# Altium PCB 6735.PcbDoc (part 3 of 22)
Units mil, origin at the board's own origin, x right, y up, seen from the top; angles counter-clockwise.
Board outline 2641.73 x 5165.35 mil, 6 copper layers (Top, Inner Layer 2, Inner Layer 3, Inner Layer 4, Inner Layer 5, Bottom), stack 35.7 mil thick; 1011 components, 790 nets, 4118 pads, 9325 vias.
Unrouted connection lines stored in the file: 4610.
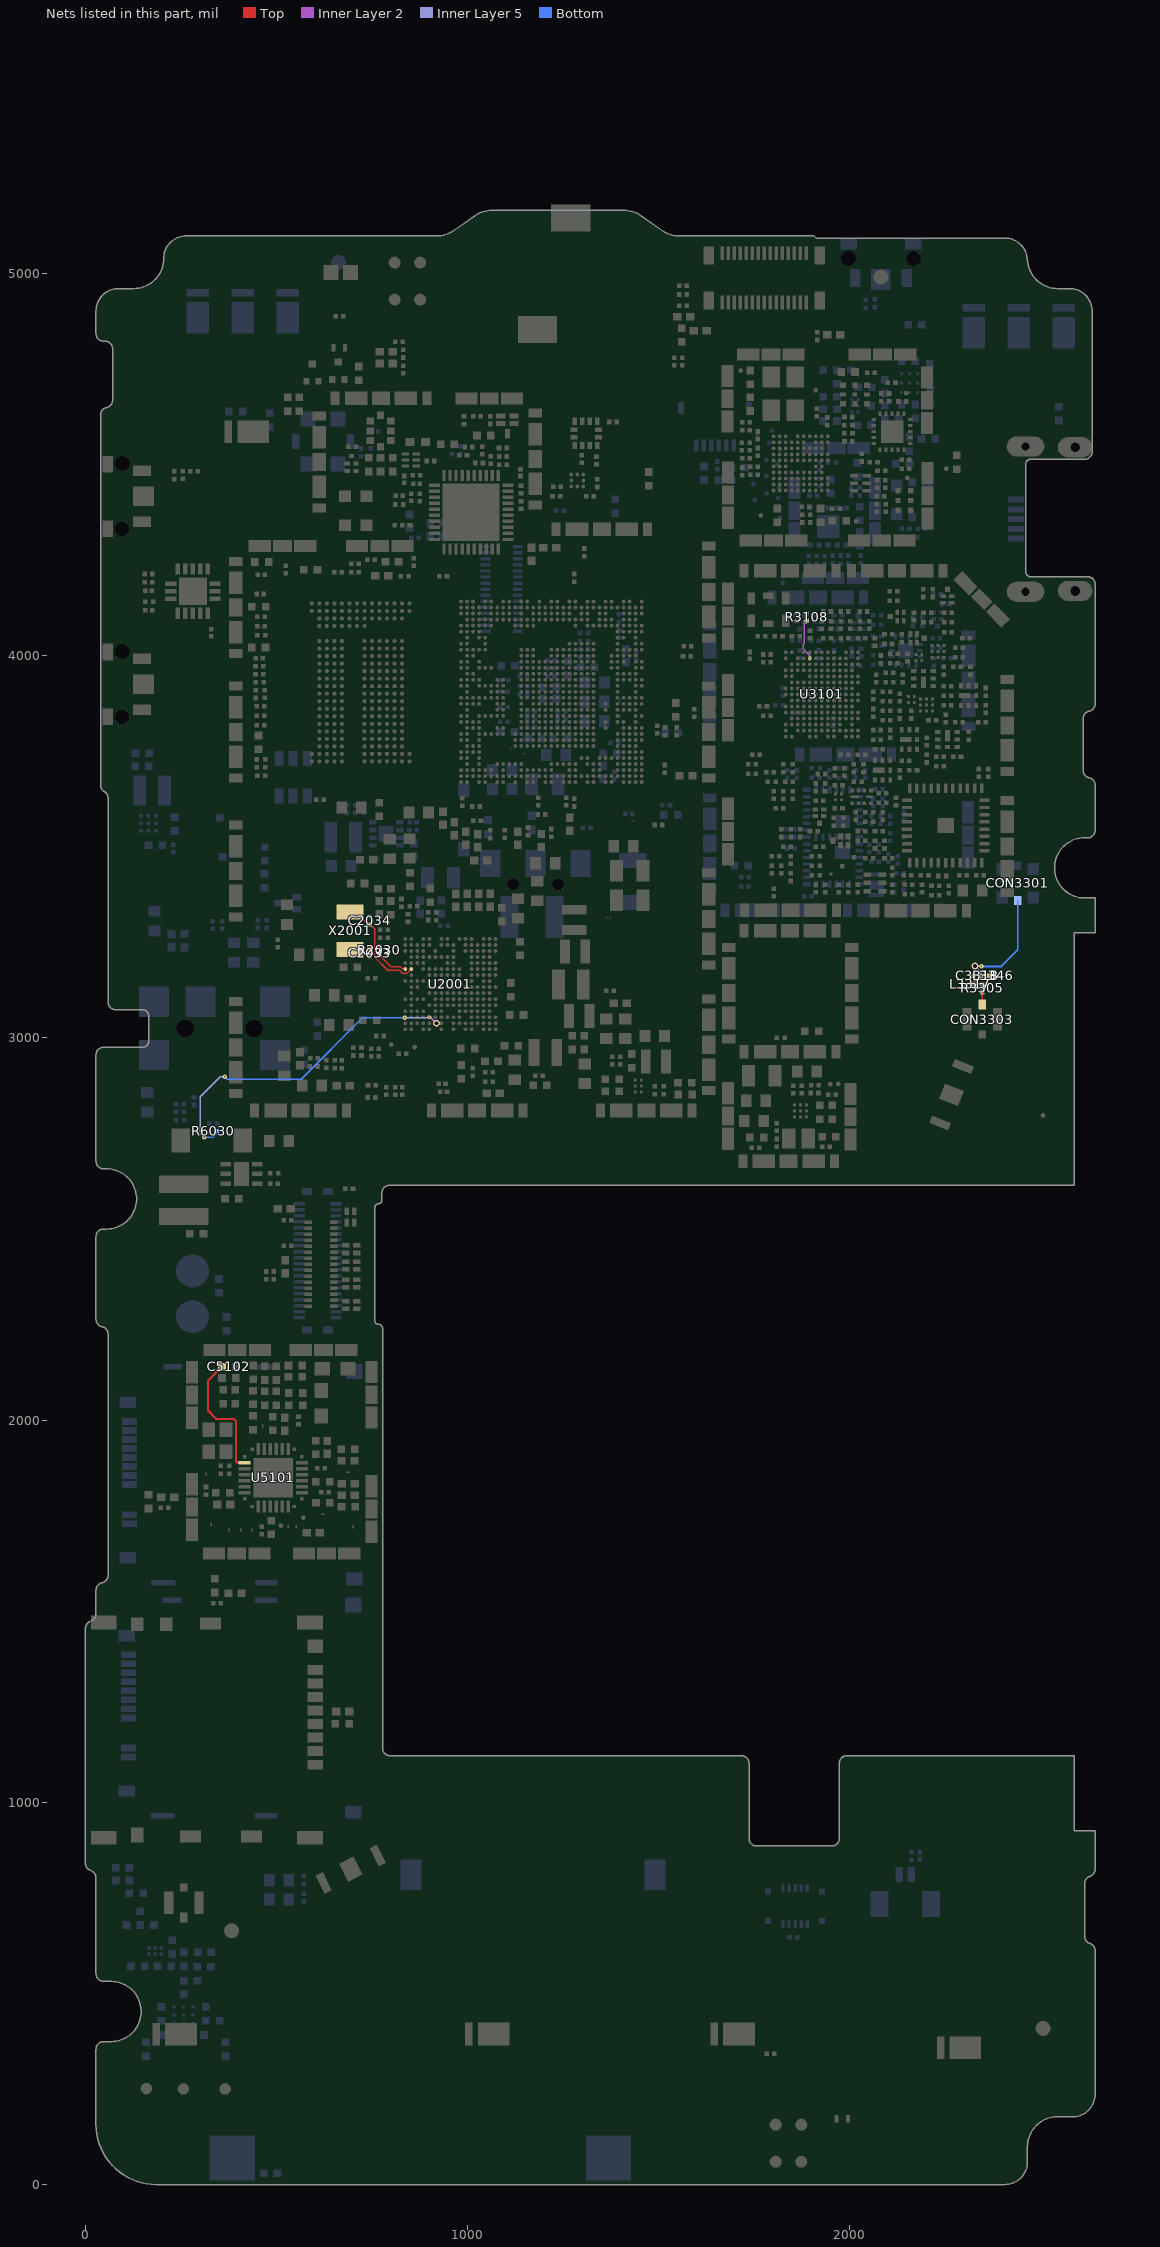
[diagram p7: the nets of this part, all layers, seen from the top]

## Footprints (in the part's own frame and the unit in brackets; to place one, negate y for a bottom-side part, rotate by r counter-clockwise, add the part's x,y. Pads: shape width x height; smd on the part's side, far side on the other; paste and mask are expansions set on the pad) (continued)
AUDIOJACK$2F$5P$2F$SMD$2F$EJ-3699M-GP [mm]
  rect 2x2 smd: 1(0,0) 2(0,-3.55) 3(-3.1,0) 4(-8.05,0) 5(-8.05,-3.55)
  round 1.2 hole 1.2 unplated: 6(-2.05,-1.775) 7(-6.65,-1.775)
  Keep-Out Layer pour cut-out: -1.196,-1.775 -1.261,-1.448 -1.446,-1.171 -1.723,-0.986 -2.05,-0.921 -2.05,-0.921 -2.377,-0.986 -2.654,-1.171 -2.839,-1.448 -2.904,-1.775 -2.904,-1.775 -2.839,-2.102 -2.654,-2.379 -2.377,-2.564 -2.05,-2.629 -2.05,-2.629 -1.723,-2.564 -1.446,-2.379 -1.261,-2.102 -1.196,-1.775
  Keep-Out Layer pour cut-out: -5.796,-1.775 -5.861,-1.448 -6.046,-1.171 -6.323,-0.986 -6.65,-0.921 -6.65,-0.921 -6.977,-0.986 -7.254,-1.171 -7.439,-1.448 -7.504,-1.775 -7.504,-1.775 -7.439,-2.102 -7.254,-2.379 -6.977,-2.564 -6.65,-2.629 -6.65,-2.629 -6.323,-2.564 -6.046,-2.379 -5.861,-2.102 -5.796,-1.775
  silkscreen extent -8.9,-5.3 3.85,1.75
BALUN$2F$SMD$2F$HHM22112A2 [mm]
  rect 0.3x0.5 smd: 1(-0.55,-0.5) 2(0,-0.5) 3(0.55,-0.5) 4(0.55,0.5) 5(0,0.5) 6(-0.55,0.5)
  silkscreen extent -1.15,-0.75 0.9,0.5
BALUN$2F$SMD$2F$TFSZ06051897-3317A1 [mm]
  rect 0.2x0.18 smd: 1(-0.2,-0.19) 2(0.2,-0.19) 3(0.2,0.19) 4(-0.2,0.19)
  silkscreen extent -0.55,-0.53 0.4,0.32
BALUN$2F$SMD$2F$TFSZ06052460-3310A2 [mm]
  rect 0.2x0.18 smd: 1(-0.2,-0.19) 2(0.2,-0.19) 3(0.2,0.19) 4(-0.2,0.19)
  silkscreen extent -0.44,-0.5 0.21,0.38
BAT$2F$SMD$2F$KBC23S3D4XR$2F$KEIRAKU [mm]
  rect 1.35x1.8 smd: 1(3,1.4) 2(0,1.4) 3(-3,1.4)
  rect 1.2x2.79 smd: 4(-1.28,-2.145) 5(1.73,-2.145)
  round 0.8 hole 0.8 unplated: 6(-1.5,0) 7(1.5,0)
  Keep-Out Layer pour cut-out: -0.846,0 -0.896,0.25 -1.038,0.462 -1.25,0.604 -1.5,0.654 -1.5,0.654 -1.75,0.604 -1.962,0.462 -2.104,0.25 -2.154,0 -2.154,0 -2.104,-0.25 -1.962,-0.462 -1.75,-0.604 -1.5,-0.654 -1.5,-0.654 -1.25,-0.604 -1.038,-0.462 -0.896,-0.25 -0.846,0
  Keep-Out Layer pour cut-out: 2.154,0 2.104,0.25 1.962,0.462 1.75,0.604 1.5,0.654 1.5,0.654 1.25,0.604 1.038,0.462 0.896,0.25 0.846,0 0.846,0 0.896,-0.25 1.038,-0.462 1.25,-0.604 1.5,-0.654 1.5,-0.654 1.75,-0.604 1.962,-0.462 2.104,-0.25 2.154,0
  silkscreen extent -4.55,-4.75 4.55,1.4
BEAD0402 [mil]
  rect 24x20 smd: 1(-20,0) 2(20,0)
  silkscreen extent -40,-15 40,15
BEAD0603 [mil]
  rect 28x32 smd: 1(-25.59,0) 2(25.59,0)
  silkscreen extent -48,-25 48,25
C0201 [mil]
  rect 12x12 smd: 1(-10,0) 2(10,0)
  silkscreen extent -20,-10 20,10
C0402 [mil]
  rect 20x20 smd: 1(-18,0) 2(18,0)
  silkscreen extent -33,-15 33,15
C0603 [mil]
  rect 28x32 smd: 1(-25.59,0) 2(25.59,0)
  silkscreen extent -48,-25 48,25
C0805 [mil]
  rect 34x56 smd: 1(-34.45,0) 2(34.45,0)
  silkscreen extent -62,-38 62,38
CABLE_CLIP$2F$3P$2F$SMD$2F$PCV1003 [mm]
  rect 1.35x0.55 smd: 1(0,-2.025) 3(0,2.025)
  rect 1.35x1.1 smd: 2(0,0)
  silkscreen extent -0.68,-1.6 0.68,1.6
CAMERA_MODULE$2F$30P$2F$SMD$2F$CM9156-B1300BA-E [mm]
  rect 0.23x0.65 smd: 1(-2.8,-1.075) 2(-2.4,-1.075) 3(-2,-1.075) 4(-1.6,-1.075) 5(-1.2,-1.075) 6(-0.8,-1.075) 7(-0.4,-1.075) 8(0,-1.075) 9(0.4,-1.075) 10(0.8,-1.075) 11(1.2,-1.075) 12(1.6,-1.075) 13(2,-1.075) 14(2.4,-1.075) 15(2.8,-1.075) 16(2.8,1.075) 17(2.4,1.075) 18(2,1.075) 19(1.6,1.075) 20(1.2,1.075) 21(0.8,1.075) 22(0.4,1.075) 23(0,1.075) 24(-0.4,1.075) 25(-0.8,1.075) 26(-1.2,1.075) 27(-1.6,1.075) 28(-2,1.075) 29(-2.4,1.075) 30(-2.8,1.075)
  Top pour cut-out: -4.3,15.95 4.35,15.95 4.35,7.25 -4.3,7.25 -4.3,15.95
  silkscreen extent -4.6,-2.35 4.6,15.95
CAMERA_MODULE$2F$30P$2F$SMD$2F$Q5V22K-0JG [mm]
  rect 0.23x0.92 smd: 1(2.8,-1.64) 2(2.8,1.64) 3(2.4,-1.64) 4(2.4,1.64) 5(2,-1.64) 6(2,1.64) 7(1.6,-1.64) 8(1.6,1.64) 9(1.2,-1.64) 10(1.2,1.64) 11(0.8,-1.64) 12(0.8,1.64) 13(0.4,-1.64) 14(0.4,1.64) 15(0,-1.64) 16(0,1.64) 17(-0.4,-1.64) 18(-0.4,1.64) 19(-0.8,-1.64) 20(-0.8,1.64) 21(-1.2,-1.64) 22(-1.2,1.64) 23(-1.6,-1.64) 24(-1.6,1.64) 25(-2,-1.64) 26(-2,1.64) 27(-2.4,-1.64) 28(-2.4,1.64) 29(-2.8,-1.64) 30(-2.8,1.64)
  rect 0.7x1.2 smd: 31(-3.7,1.5) 32(-3.7,-1.5) 33(3.7,-1.5) 34(3.7,1.5)
  silkscreen extent -4.45,-2.95 4.65,14.25
CITIZENLS10_BOSS [mm]
  rect 1.2x0.7 smd: 1(-1.3,1.7) 2(-1.3,-1.7)
  rect 1.4x1.3 smd: 3(-1.405,0.001)
  rect 0.7x1.1 smd: 4(0.95,2.15) 5(0.95,-2.15)
  round 1 hole 1 unplated: 6(0.013,2.172) 7(0.001,-2.172)
  Keep-Out Layer pour cut-out: 0.763,2.172 0.706,2.459 0.543,2.702 0.3,2.865 0.013,2.922 0.013,2.922 -0.274,2.865 -0.517,2.702 -0.68,2.459 -0.737,2.172 -0.737,2.172 -0.68,1.885 -0.517,1.642 -0.274,1.479 0.013,1.422 0.013,1.422 0.3,1.479 0.543,1.642 0.706,1.885 0.763,2.172
  Keep-Out Layer pour cut-out: 0.751,-2.172 0.694,-1.885 0.531,-1.642 0.288,-1.479 0.001,-1.422 0.001,-1.422 -0.286,-1.479 -0.529,-1.642 -0.692,-1.885 -0.749,-2.172 -0.749,-2.172 -0.692,-2.459 -0.529,-2.702 -0.286,-2.865 0.001,-2.922 0.001,-2.922 0.288,-2.865 0.531,-2.702 0.694,-2.459 0.751,-2.172
  silkscreen extent -1.15,-2.35 2.35,2.35
COAXIAL$2F$SMD$2F$TA-RF02-001-03-811 [mm]
  rect 0.5x0.55 smd: 1(0,1.025)
  rect 0.5x0.65 smd: 2(0,-0.975)
  rect 0.6x1.5 smd: 3(-1,0) 4(1,0)
  silkscreen extent -0.55,-0.9 0.65,1.15
CON5X2$2F$SMD$2F$P0.4$2F$F$2F$AXE510127 [mm]
  rect 0.23x0.5 smd: 1(-0.8,-1.2) 2(-0.8,1.2) 3(-0.4,-1.2) 4(-0.4,1.2) 5(0,-1.2) 6(0,1.2) 7(0.4,-1.2) 8(0.4,1.2) 9(0.8,-1.2) 10(0.8,1.2)
  rect 0.4x0.4 smd: 11(-1.8,0.99) 12(-1.8,-0.99) 13(1.8,-0.99) 14(1.8,0.99)
  Top region: 2.25,-1.15 1.95,-1.45 1.35,-1.45 1.35,-0.53 2.25,-0.53 2.25,-1.15
  Top region: -2.25,1.15 -1.95,1.45 -1.35,1.45 -1.35,0.53 -2.25,0.53 -2.25,1.15
  Top region: -2.25,-1.15 -1.95,-1.45 -1.35,-1.45 -1.35,-0.53 -2.25,-0.53 -2.25,-1.15
  Top region: 2.25,1.15 1.95,1.45 1.35,1.45 1.35,0.53 2.25,0.53 2.25,1.15
  silkscreen extent -2.3,-0.45 2.3,0.45
CON15X2$2F$SMD$2F$F$2F$P0.4$2F$24-5804-030-000-829HT [mm]
  rect 0.23x0.5 smd: 1(-2.8,-0.85) 2(-2.4,-0.85) 3(-2,-0.85) 4(-1.6,-0.85) 5(-1.2,-0.85) 6(-0.8,-0.85) 7(-0.4,-0.85) 8(0,-0.85) 9(0.4,-0.85) 10(0.8,-0.85) 11(1.2,-0.85) 12(1.6,-0.85) 13(2,-0.85) 14(2.4,-0.85) 15(2.8,-0.85) 16(2.8,0.85) 17(2.4,0.85) 18(2,0.85) 19(1.6,0.85) 20(1.2,0.85) 21(0.8,0.85) 22(0.4,0.85) 23(0,0.85) 24(-0.4,0.85) 25(-0.8,0.85) 26(-1.2,0.85) 27(-1.6,0.85) 28(-2,0.85) 29(-2.4,0.85) 30(-2.8,0.85)
  silkscreen extent -4.2,-1.4 3.93,1.15
CON20X2$2F$SMD$2F$M$2F$AXT640124$2F$FPC [mm]
  rect 0.23x0.75 smd: 1(-3.8,-1.225) 2(-3.8,1.225) 3(-3.4,-1.225) 4(-3.4,1.225) 5(-3,-1.225) 6(-3,1.225) 7(-2.6,-1.225) 8(-2.6,1.225) 9(-2.2,-1.225) 10(-2.2,1.225) 11(-1.8,-1.225) 12(-1.8,1.225) 13(-1.4,-1.225) 14(-1.4,1.225) 15(-1,-1.225) 16(-1,1.225) 17(-0.6,-1.225) 18(-0.6,1.225) 19(-0.2,-1.225) 20(-0.2,1.225) 21(0.2,-1.225) 22(0.2,1.225) 23(0.6,-1.225) 24(0.6,1.225) 25(1,-1.225) 26(1,1.225) 27(1.4,-1.225) 28(1.4,1.225) 29(1.8,-1.225) 30(1.8,1.225) 31(2.2,-1.225) 32(2.2,1.225) 33(2.6,-1.225) 34(2.6,1.225) 35(3,-1.225) 36(3,1.225) 37(3.4,-1.225) 38(3.4,1.225) 39(3.8,-1.225) 40(3.8,1.225)
  rect 0.45x0.655 smd: 41(-4.6,0.703) 42(-4.6,-0.703) 43(4.6,-0.703) 44(4.6,0.703)
  silkscreen extent -6.55,-16.75 6.55,3.25
CRYS$2F$SMD$2F$3.2X1.5$2F$9H032000XX$2F$TXC [mm]
  rect 1x1.8 smd: 1(-1.25,0) 2(1.25,0)
  silkscreen extent -0.6,-0.85 0.6,0.85
CRYS$2F$SMD$2F$FA-128 [mm]
  rect 0.95x0.85 smd: 1(-0.725,-0.575) 2(0.725,-0.575) 3(0.725,0.575) 4(-0.725,0.575)
  silkscreen extent -1.35,-1.15 1.1,0.9
DIODE$2F$SMD$2F$MMSZ5221B [mm]
  rect 0.95x0.75 smd: A(1.95,0) K(-1.95,0)
  silkscreen extent -1.53,-0.95 1.53,0.95
DIPLEXER$2F$6P$2F$SMD$2F$FI212P0829G2 [mm]
  rect 0.35x0.35 smd: 1(-0.65,0.425) 2(0,0.425) 3(0.65,0.425) 4(0.65,-0.425) 5(0,-0.425) 6(-0.65,-0.425)
  silkscreen extent -1.38,-0.75 1.12,1
DSBGA9$2F$P0.4$2F$B0.225$2F$LM3242 [mm]
  round 0.225 smd: A1(-0.4,0.4) A2(0,0.4) A3(0.4,0.4) B1(-0.4,0) B2(0,0) B3(0.4,0) C1(-0.4,-0.4) C2(0,-0.4) C3(0.4,-0.4)
  silkscreen extent -1.05,-0.74 0.8,0.99
DSBGA9$2F$SMD$2F$P0.5$2F$LM3642 [mm]
  round 0.27 smd: A1(-0.5,0.5) A2(0,0.5) A3(0.5,0.5) B1(-0.5,0) B2(0,0) B3(0.5,0) C1(-0.5,-0.5) C2(0,-0.5) C3(0.5,-0.5)
  silkscreen extent -1.14,-0.9 0.88,1.14
DUPLEXER$2F$8P$2F$SMD$2F$SAYEY710MBA0F0A [mm]
  rect 0.35x0.25 smd: 1(-0.65,-0.5) 3(0.65,-0.5) 4(0.65,0) 5(0.65,0.5) 6(0,0.5) 7(-0.65,0.5) 8(-0.65,0)
  rect 0.35x0.75 smd: 2(0,-0.25)
  silkscreen extent -1.25,-1.05 1,0.8
FBGA221$2F$P0.5$2F$B0.27$2F$11.5X13$2F$SAMSUNG [mm]
  round 0.27 smd: A1(-3.25,5.25) A2(-2.75,5.25) A3(-2.25,5.25) A4(-1.75,5.25) A5(-1.25,5.25) A6(-0.75,5.25) A7(-0.25,5.25) A8(0.25,5.25) A9(0.75,5.25) A10(1.25,5.25) A11(1.75,5.25) A12(2.25,5.25) A13(2.75,5.25) A14(3.25,5.25) AA1(-3.25,-4.75) AA2(-2.75,-4.75) AA3(-2.25,-4.75) AA4(-1.75,-4.75) AA5(-1.25,-4.75) AA8(0.25,-4.75) AA9(0.75,-4.75) AA10(1.25,-4.75) AA11(1.75,-4.75) AA12(2.25,-4.75) AA13(2.75,-4.75) AA14(3.25,-4.75) AB1(-3.25,-5.25) AB2(-2.75,-5.25) AB3(-2.25,-5.25) AB4(-1.75,-5.25) AB5(-1.25,-5.25) AB8(0.25,-5.25) AB9(0.75,-5.25) AB10(1.25,-5.25) AB11(1.75,-5.25) AB12(2.25,-5.25) AB13(2.75,-5.25) AB14(3.25,-5.25) B1(-3.25,4.75) B2(-2.75,4.75) B3(-2.25,4.75) B4(-1.75,4.75) B5(-1.25,4.75) B6(-0.75,4.75) B7(-0.25,4.75) B8(0.25,4.75) B9(0.75,4.75) B10(1.25,4.75) B11(1.75,4.75) B12(2.25,4.75) B13(2.75,4.75) B14(3.25,4.75) C2(-2.75,4.25) C3(-2.25,4.25) C4(-1.75,4.25) C5(-1.25,4.25) C6(-0.75,4.25) C7(-0.25,4.25) C8(0.25,4.25) C9(0.75,4.25) C10(1.25,4.25) C11(1.75,4.25) C12(2.25,4.25) C13(2.75,4.25) D2(-2.75,3.75) D3(-2.25,3.75) D4(-1.75,3.75) D5(-1.25,3.75) D6(-0.75,3.75) D7(-0.25,3.75) D8(0.25,3.75) F2(-2.75,2.75) F3(-2.25,2.75) F4(-1.75,2.75) F5(-1.25,2.75) F8(0.25,2.75) F9(0.75,2.75) F10(1.25,2.75) F11(1.75,2.75) F12(2.25,2.75) F13(2.75,2.75) G2(-2.75,2.25) G3(-2.25,2.25) G4(-1.75,2.25) G5(-1.25,2.25) G8(0.25,2.25) G9(0.75,2.25) G10(1.25,2.25) G11(1.75,2.25) G12(2.25,2.25) G13(2.75,2.25) H2(-2.75,1.75) H3(-2.25,1.75) H4(-1.75,1.75) H5(-1.25,1.75) H8(0.25,1.75) H9(0.75,1.75) H10(1.25,1.75) H11(1.75,1.75) H12(2.25,1.75) H13(2.75,1.75) J2(-2.75,1.25) J3(-2.25,1.25) J4(-1.75,1.25) J5(-1.25,1.25) J8(0.25,1.25) J9(0.75,1.25) J10(1.25,1.25) J11(1.75,1.25) J12(2.25,1.25) J13(2.75,1.25) K2(-2.75,0.75) K3(-2.25,0.75) K4(-1.75,0.75) K5(-1.25,0.75) K8(0.25,0.75) K9(0.75,0.75) K10(1.25,0.75) K11(1.75,0.75) K12(2.25,0.75) K13(2.75,0.75) L2(-2.75,0.25) L3(-2.25,0.25) L4(-1.75,0.25) L5(-1.25,0.25) L8(0.25,0.25) L9(0.75,0.25) L10(1.25,0.25) L11(1.75,0.25) L12(2.25,0.25) L13(2.75,0.25) M2(-2.75,-0.25) M3(-2.25,-0.25) M4(-1.75,-0.25) M5(-1.25,-0.25) M8(0.25,-0.25) M9(0.75,-0.25) M10(1.25,-0.25) M11(1.75,-0.25) M12(2.25,-0.25) M13(2.75,-0.25) N2(-2.75,-0.75) N3(-2.25,-0.75) N4(-1.75,-0.75) N5(-1.25,-0.75) N8(0.25,-0.75) N9(0.75,-0.75) N10(1.25,-0.75) N11(1.75,-0.75) N12(2.25,-0.75) N13(2.75,-0.75) P2(-2.75,-1.25) P3(-2.25,-1.25) P4(-1.75,-1.25) P5(-1.25,-1.25) P8(0.25,-1.25) P9(0.75,-1.25) P10(1.25,-1.25) P11(1.75,-1.25) P12(2.25,-1.25) P13(2.75,-1.25) R2(-2.75,-1.75) R3(-2.25,-1.75) R4(-1.75,-1.75) R5(-1.25,-1.75) R8(0.25,-1.75) R9(0.75,-1.75) R10(1.25,-1.75) R11(1.75,-1.75) R12(2.25,-1.75) R13(2.75,-1.75) T2(-2.75,-2.25) T3(-2.25,-2.25) T4(-1.75,-2.25) T5(-1.25,-2.25) T8(0.25,-2.25) T9(0.75,-2.25) T10(1.25,-2.25) T11(1.75,-2.25) T12(2.25,-2.25) T13(2.75,-2.25) U2(-2.75,-2.75) U3(-2.25,-2.75) U4(-1.75,-2.75) U5(-1.25,-2.75) U8(0.25,-2.75) U9(0.75,-2.75) U10(1.25,-2.75) U11(1.75,-2.75) U12(2.25,-2.75) U13(2.75,-2.75) V2(-2.75,-3.25) V3(-2.25,-3.25) V4(-1.75,-3.25) V5(-1.25,-3.25) V8(0.25,-3.25) V9(0.75,-3.25) V10(1.25,-3.25) V11(1.75,-3.25) V12(2.25,-3.25) V13(2.75,-3.25) W2(-2.75,-3.75) W3(-2.25,-3.75) W4(-1.75,-3.75) W5(-1.25,-3.75) W8(0.25,-3.75) W9(0.75,-3.75) W10(1.25,-3.75) W11(1.75,-3.75) W12(2.25,-3.75) W13(2.75,-3.75) Y2(-2.75,-4.25) Y3(-2.25,-4.25) Y4(-1.75,-4.25) Y5(-1.25,-4.25) Y8(0.25,-4.25) Y9(0.75,-4.25) Y10(1.25,-4.25) Y11(1.75,-4.25) Y12(2.25,-4.25) Y13(2.75,-4.25)
  silkscreen extent -6.1,-6.6 5.85,6.85
FD [mm]
  round 1 smd: 1(0,0)
  Top pour cut-out: 1.168,0 1.079,0.447 0.826,0.826 0.447,1.079 0,1.168 0,1.168 -0.447,1.079 -0.826,0.826 -1.079,0.447 -1.168,0 -1.168,0 -1.079,-0.447 -0.826,-0.826 -0.447,-1.079 0,-1.168 0,-1.168 0.447,-1.079 0.826,-0.826 1.079,-0.447 1.168,0
FILTER$2F$SMD$2F$885049 [mm]
  rect 0.35x0.425 smd: 1(-0.5,0) 2(0,-0.288) 3(0.5,-0.288) 4(0.5,0.288) 5(0,0.288)
  silkscreen extent -1.05,-0.65 0.75,0.65
FILTER$2F$SMD$2F$ACPF-7124 [mm]
  rect 0.66x0.325 smd: 1(-0.671,0)
  rect 0.32x0.625 smd: 2(0,-0.437) 3(0.5,-0.437) 4(0.5,0.437) 5(0,0.437)
  silkscreen extent -1.27,-0.64 0.79,0.64
FILTER$2F$SMD$2F$FI-168L083523-T [mm]
  rect 0.25x0.55 smd: 1(-0.5,-0.425) 2(0,-0.425) 3(0.5,-0.425) 4(0.5,0.425) 5(0,0.425) 6(-0.5,0.425)
  silkscreen extent -1.15,-0.75 0.9,0.5
FILTER$2F$SMD$2F$LFB212G49CG7D755 [mm]
  rect 0.275x0.95 smd: 1(-0.687,0) 3(0.687,0)
  rect 0.6x0.95 smd: 2(0,0)
  silkscreen extent -1.38,-0.72 1.12,0.97
FILTER$2F$SMD$2F$LFD211G57ME3 [mm]
  rect 0.47x0.5 smd: 1(-0.65,-0.675) 2(0,-0.675) 3(0.65,-0.675) 5(0.65,0.675) 6(0,0.675) 7(-0.65,0.675)
  rect 0.5x0.47 smd: 4(1.05,0) 8(-1.05,0)
  silkscreen extent -1.38,-1 1.12,0.75
FILTER$2F$SMD$2F$SPU0410HR5H-PB [mm]
  round 0.8 smd: 1(0.85,1.23) 2(0.85,-1.23) 3(-0.85,-1.23) 4(-0.85,1.23)
  silkscreen extent -1.58,-1.98 1.8,2.25
FLASH_LED$2F$LUW_F8DN [mm]
  rect 0.5x0.5 smd: 1(-0.1,-1.6) 2(0.1,1)
  Top region: -1.9,-1.15 1.9,-1.15 1.9,-2 -1.9,-2 -1.9,-1.15
  Top region: -1.9,2 1.9,2 1.9,0.075 0.862,0.079 0.779,0.063 0.709,0.016 0.662,-0.054 0.646,-0.137 0.65,-0.137 0.65,-0.65 -0.65,-0.65 -0.646,-0.137 -0.662,-0.054 -0.709,0.016 -0.779,0.063 -0.862,0.079 -0.862,0.075 -1.9,0.075 -1.9,2
  silkscreen extent -2.02,-2.07 2.02,2.07
H2$2F$SMD$2F$P0.8$2F$SM02B-SURS-TF$2F$SUR [mm]
  rect 0.5x1 smd: 1(-0.4,0) 2(0.4,0)
  rect 1.2x1.7 smd: 3(-1.7,-1.95) 4(1.7,-1.95)
  silkscreen extent -1.95,-2.45 1.95,0.3
H6$2F$SMD$2F$P0.5$2F$FH34S-06S-0.5SH [mm]
  rect 0.3x0.8 smd paste-0.025: 1(-1.25,0) 2(-0.75,0) 3(-0.25,0) 4(0.25,0) 5(0.75,0) 6(1.25,0)
  rect 0.4x0.8 smd: 7(-2.25,-2.5) 8(2.25,-2.5)
  silkscreen extent -2.55,-3.1 2.55,0.65
L0201 [mil]
  rect 12x12 smd: 1(-10,0) 2(10,0)
  silkscreen extent -20,-10 20,10
L0402 [mil]
  rect 20x20 smd: 1(-18,0) 2(18,0)
  silkscreen extent -33,-15 33,15
L$2F$CHOKE$2F$SMD$2F$DLP0NS0806 [mm]
  rect 0.5x0.3 smd: 1(-0.375,-0.25) 2(0.375,-0.25) 3(0.375,0.25) 4(-0.375,0.25)
  silkscreen extent -0.85,-0.75 0.4,0.5
L$2F$CHOKE$2F$SMD$2F$LQH3NP [mm]
  rect 1.15x3.3 smd: 1(-1.075,0) 2(1.075,0)
  silkscreen extent -1.8,-1.78 1.8,1.8
L$2F$IND$2F$SMD$2F$0603 [mil]
  rect 40x35 smd: 1(-33.5,0) 2(33.5,0)
  silkscreen extent -65,-25 65,25
L$2F$IND$2F$SMD$2F$2016 [mm]
  rect 0.7x1.8 smd: 1(-0.75,0) 2(0.75,0)
  silkscreen extent -1.4,-1.2 1.4,1.2
L$2F$IND$2F$SMD$2F$2520 [mm]
  rect 0.85x2 smd: 1(-0.825,0) 2(0.825,0)
  silkscreen extent -1.4,-1.15 1.4,1.15
L$2F$IND$2F$SMD$2F$LQM21PNR54MG0 [mm]
  rect 1.32x0.9 smd: 1(0,-0.64) 2(0,0.64)
  silkscreen extent -1,-1.38 0.75,1.12
L$2F$IND$2F$SMD$2F$VLS201610E [mm]
  rect 0.65x1.6 smd: 1(-0.675,0) 2(0.675,0)
  silkscreen extent -1.1,-0.9 1.1,0.9
LED190 [mm]
  rect 1x1 smd: 1(0.65,0) 2(-0.65,0)
  silkscreen extent -1.2,-0.6 1.9,0.6
LGA12$2F$SMD$2F$P0.5$2F$MC3410 [mm]
  rect 0.3x0.475 smd: 1(-0.75,-0.813) 2(-0.25,-0.813) 3(0.25,-0.813) 4(0.75,-0.813) 7(0.75,0.813) 8(0.25,0.813) 9(-0.25,0.813) 10(-0.75,0.813)
  rect 0.475x0.3 smd: 5(0.813,-0.25) 6(0.813,0.25) 11(-0.813,0.25) 12(-0.813,-0.25)
  silkscreen extent -1.3,-1.3 1.05,1.05
MICROSD$2F$8P$2F$SMD$2F$TA-M017-012-07-811 [mm]
  rect 0.65x1 smd: 1(0,-0.5) 2(-0.9,-0.5) 3(-1.8,-0.5) 4(-2.7,-0.5) 5(-3.6,-0.5) 6(-4.5,-0.5) 7(-5.4,-0.5) 8(-6.3,-0.5)
  rect 1x0.85 smd: 9(4.675,-12.325)
  rect 0.9x0.85 smd: 10(-9.325,-12.325) 11(-9.325,-10.4)
  rect 0.9x1 smd: 12(-7.875,-0.5)
  rect 0.9x1.7 smd: 13(-9.45,-14.55) 14(4.85,-14.55) 15(4.85,-0.85) 16(-9.45,-0.85)
  rect 0.8x1.4 smd: 17(4.775,-8.8) 18(4.775,-4.75) 19(-9.375,-7.45)
  silkscreen extent -9.85,-15.6 5.25,0
MICROUSB$2F$5P$2F$SMD$2F$P0.65$2F$R$2F$KIU90511S1R [mm]
  rect 0.4x1.05 smd: 1(-1.3,0) 2(-0.65,0) 3(0,0) 4(0.65,0) 5(1.3,0)
  oval 1.35x2.5 hole 0.55 slot 1.7 at 90 deg: 6(-4.825,-0.625) 7(4.825,-0.625)
  oval 1.35x2.3 hole 0.65 slot 1.7 at 90 deg: 8(4.775,-3.925) 9(-4.775,-3.925)
  silkscreen extent -3.75,-6.48 3.75,0
MM8130-2602 [mm]
  rect 0.5x0.58 smd: 1(0,1.16) 2(0,-1.16)
  rect 0.75x0.8 smd: 3(-1.025,0.95) 4(-1.025,-0.95) 5(1.025,0.95) 6(1.025,-0.95)
  silkscreen extent -1.3,-1.7 1.4,1.3
MM8430-2600B [mm]
  rect 1x0.5 smd: 1(0,1.8) 2(0,-1.8)
  rect 1x1 smd: 3(-1.5,1) 4(-1.5,-1) 5(1.5,1) 6(1.5,-1)
  Top region: -0.5,2.05 -0.5,1.55 -0.25,1.55 -0.25,1.05 0.25,1.05 0.25,1.55 0.5,1.55 0.5,2.05 -0.5,2.05
  Top region: 0.5,-2.05 0.5,-1.55 0.25,-1.55 0.25,-1.05 -0.25,-1.05 -0.25,-1.55 -0.5,-1.55 -0.5,-2.05 0.5,-2.05
  silkscreen extent -1.55,-1.55 1.55,1.55
MT6158$2F$VFBGA91$2F$P0.4$2F$B0.25$2F$4.2X4.2 [mm]
  round 0.25 smd mask+0.038: A1(-1.8,1.8) A2(-1.4,1.8) A4(-0.6,1.8) A5(-0.2,1.8) A8(1,1.8) A9(1.4,1.8) A10(1.8,1.8) B1(-1.8,1.4) B2(-1.4,1.4) B3(-1,1.4) B4(-0.6,1.4) B5(-0.2,1.4) B6(0.2,1.4) B7(0.6,1.4) B8(1,1.4) B9(1.4,1.4) B10(1.8,1.4) C1(-1.8,1) C2(-1.4,1) C3(-1,1) C4(-0.6,1) C5(-0.2,1) C6(0.2,1) C7(0.6,1) C8(1,1) C9(1.4,1) C10(1.8,1) D1(-1.8,0.6) D3(-1,0.6) D4(-0.6,0.6) D5(-0.2,0.6) D7(0.6,0.6) D8(1,0.6) D9(1.4,0.6) D10(1.8,0.6) E1(-1.8,0.2) E2(-1.4,0.2) E3(-1,0.2) E4(-0.6,0.2) E5(-0.2,0.2) E7(0.6,0.2) E8(1,0.2) E9(1.4,0.2) E10(1.8,0.2) F1(-1.8,-0.2) F2(-1.4,-0.2) F3(-1,-0.2) F4(-0.6,-0.2) F5(-0.2,-0.2) F7(0.6,-0.2) F8(1,-0.2) F9(1.4,-0.2) F10(1.8,-0.2) G2(-1.4,-0.6) G3(-1,-0.6) G4(-0.6,-0.6) G5(-0.2,-0.6) G7(0.6,-0.6) G8(1,-0.6) G9(1.4,-0.6) G10(1.8,-0.6) H1(-1.8,-1) H2(-1.4,-1) H3(-1,-1) H4(-0.6,-1) H5(-0.2,-1) H6(0.2,-1) H7(0.6,-1) H8(1,-1) H9(1.4,-1) H10(1.8,-1) J1(-1.8,-1.4) J2(-1.4,-1.4) J3(-1,-1.4) J4(-0.6,-1.4) J5(-0.2,-1.4) J6(0.2,-1.4) J7(0.6,-1.4) J8(1,-1.4) J9(1.4,-1.4) J10(1.8,-1.4) K1(-1.8,-1.8) K2(-1.4,-1.8) K3(-1,-1.8) K4(-0.6,-1.8) K5(-0.2,-1.8) K6(0.2,-1.8) K7(0.6,-1.8) K8(1,-1.8) K9(1.4,-1.8) K10(1.8,-1.8)
  Top pour cut-out: 2.2,2.2 -2.2,2.2 -2.2,-2.2 2.2,-2.2 2.2,2.2
  silkscreen extent -2.45,-2.2 2.2,2.45
MT6169$2F$VFBGA175$2F$P0.4$2F$B0.25$2F$6.2X5.4 [mm]
  round 0.25 smd mask+0.038: A1(-2.8,2.4) A2(-2.4,2.4) A3(-2,2.4) A5(-1.2,2.4) A6(-0.8,2.4) A8(0,2.4) A9(0.4,2.4) A11(1.2,2.4) A12(1.6,2.4) A14(2.4,2.4) A15(2.8,2.4) B1(-2.8,2) B3(-2,2) B4(-1.6,2) B5(-1.2,2) B6(-0.8,2) B7(-0.4,2) B8(0,2) B9(0.4,2) B10(0.8,2) B11(1.2,2) B12(1.6,2) B13(2,2) B14(2.4,2) B15(2.8,2) C1(-2.8,1.6) C2(-2.4,1.6) C3(-2,1.6) C4(-1.6,1.6) C5(-1.2,1.6) C6(-0.8,1.6) C7(-0.4,1.6) C8(0,1.6) C9(0.4,1.6) C10(0.8,1.6) C11(1.2,1.6) C12(1.6,1.6) C14(2.4,1.6) C15(2.8,1.6) D2(-2.4,1.2) D3(-2,1.2) D4(-1.6,1.2) D5(-1.2,1.2) D6(-0.8,1.2) D7(-0.4,1.2) D8(0,1.2) D9(0.4,1.2) D10(0.8,1.2) D11(1.2,1.2) D12(1.6,1.2) D13(2,1.2) D14(2.4,1.2) E1(-2.8,0.8) E2(-2.4,0.8) E3(-2,0.8) E4(-1.6,0.8) E5(-1.2,0.8) E6(-0.8,0.8) E7(-0.4,0.8) E8(0,0.8) E9(0.4,0.8) E10(0.8,0.8) E11(1.2,0.8) E12(1.6,0.8) E13(2,0.8) E14(2.4,0.8) E15(2.8,0.8) F1(-2.8,0.4) F2(-2.4,0.4) F3(-2,0.4) F4(-1.6,0.4) F5(-1.2,0.4) F6(-0.8,0.4) F7(-0.4,0.4) F8(0,0.4) F9(0.4,0.4) F10(0.8,0.4) F11(1.2,0.4) F12(1.6,0.4) F13(2,0.4) F14(2.4,0.4) F15(2.8,0.4) G1(-2.8,0) G2(-2.4,0) G3(-2,0) G4(-1.6,0) G5(-1.2,0) G6(-0.8,0) G7(-0.4,0) G8(0,0) G9(0.4,0) G10(0.8,0) G11(1.2,0) G12(1.6,0) G13(2,0) G14(2.4,0) H1(-2.8,-0.4) H2(-2.4,-0.4) H3(-2,-0.4) H4(-1.6,-0.4) H5(-1.2,-0.4) H6(-0.8,-0.4) H7(-0.4,-0.4) H8(0,-0.4) H9(0.4,-0.4) H10(0.8,-0.4) H11(1.2,-0.4) H12(1.6,-0.4) H13(2,-0.4) H14(2.4,-0.4) H15(2.8,-0.4) J1(-2.8,-0.8) J2(-2.4,-0.8) J3(-2,-0.8) J4(-1.6,-0.8) J5(-1.2,-0.8) J6(-0.8,-0.8) J7(-0.4,-0.8) J8(0,-0.8) J9(0.4,-0.8) J10(0.8,-0.8) J11(1.2,-0.8) J12(1.6,-0.8) J13(2,-0.8) J14(2.4,-0.8) J15(2.8,-0.8) K1(-2.8,-1.2) K2(-2.4,-1.2) K3(-2,-1.2) K4(-1.6,-1.2) K6(-0.8,-1.2) K7(-0.4,-1.2) K8(0,-1.2) K9(0.4,-1.2) K10(0.8,-1.2) K11(1.2,-1.2) K12(1.6,-1.2) K13(2,-1.2) K14(2.4,-1.2) L2(-2.4,-1.6) L3(-2,-1.6) L4(-1.6,-1.6) L6(-0.8,-1.6) L7(-0.4,-1.6) L8(0,-1.6) L9(0.4,-1.6) L10(0.8,-1.6) L11(1.2,-1.6) L12(1.6,-1.6) L13(2,-1.6) L14(2.4,-1.6) M1(-2.8,-2) M3(-2,-2) M4(-1.6,-2) M5(-1.2,-2) M6(-0.8,-2) M7(-0.4,-2) M8(0,-2) M9(0.4,-2) M10(0.8,-2) M11(1.2,-2) M12(1.6,-2) M13(2,-2) M15(2.8,-2) N1(-2.8,-2.4) N2(-2.4,-2.4) N4(-1.6,-2.4) N5(-1.2,-2.4) N7(-0.4,-2.4) N8(0,-2.4) N10(0.8,-2.4) N11(1.2,-2.4) N13(2,-2.4) N14(2.4,-2.4) N15(2.8,-2.4)
  Top pour cut-out: 3.2,2.8 -3.2,2.8 -3.2,-2.8 3.2,-2.8 3.2,2.8
  silkscreen extent -3.45,-2.8 3.2,3.05
MT6328$2F$VFBGA206$2F$P0.4$2F$B0.25$2F$6.6X6.6 [mm]
  round 0.25 smd mask+0.038: A1(-3,3) A2(-2.6,3) A3(-2.2,3) A5(-1.4,3) A6(-1,3) A7(-0.6,3) A9(0.2,3) A11(1,3) A12(1.4,3) A14(2.2,3) A15(2.6,3) A16(3,3) B1(-3,2.6) B2(-2.6,2.6) B3(-2.2,2.6) B4(-1.8,2.6) B5(-1.4,2.6) B6(-1,2.6) B7(-0.6,2.6) B8(-0.2,2.6) B9(0.2,2.6) B10(0.6,2.6) B11(1,2.6) B12(1.4,2.6) B13(1.8,2.6) B14(2.2,2.6) B15(2.6,2.6) B16(3,2.6) C1(-3,2.2) C2(-2.6,2.2) C3(-2.2,2.2) C4(-1.8,2.2) C5(-1.4,2.2) C6(-1,2.2) C7(-0.6,2.2) C8(-0.2,2.2) C9(0.2,2.2) C10(0.6,2.2) C11(1,2.2) C12(1.4,2.2) C13(1.8,2.2) C14(2.2,2.2) C15(2.6,2.2) C16(3,2.2) D2(-2.6,1.8) D3(-2.2,1.8) D4(-1.8,1.8) D5(-1.4,1.8) D6(-1,1.8) D7(-0.6,1.8) D9(0.2,1.8) D10(0.6,1.8) D11(1,1.8) D12(1.4,1.8) D13(1.8,1.8) D14(2.2,1.8) D15(2.6,1.8) E1(-3,1.4) E2(-2.6,1.4) E3(-2.2,1.4) E4(-1.8,1.4) E5(-1.4,1.4) E6(-1,1.4) E7(-0.6,1.4) E8(-0.2,1.4) E9(0.2,1.4) E10(0.6,1.4) E11(1,1.4) E12(1.4,1.4) E13(1.8,1.4) E14(2.2,1.4) E15(2.6,1.4) E16(3,1.4) F1(-3,1) F2(-2.6,1) F3(-2.2,1) F9(0.2,1) F10(0.6,1) F11(1,1) F12(1.4,1) F13(1.8,1) F15(2.6,1) F16(3,1) G1(-3,0.6) G6(-1,0.6) G7(-0.6,0.6) G8(-0.2,0.6) G9(0.2,0.6) G10(0.6,0.6) G11(1,0.6) G12(1.4,0.6) G13(1.8,0.6) G14(2.2,0.6) G15(2.6,0.6) H2(-2.6,0.2) H3(-2.2,0.2) H4(-1.8,0.2) H5(-1.4,0.2) H6(-1,0.2) H7(-0.6,0.2) H8(-0.2,0.2) H9(0.2,0.2) H10(0.6,0.2) H11(1,0.2) H12(1.4,0.2) H14(2.2,0.2) H15(2.6,0.2) H16(3,0.2) J1(-3,-0.2) J2(-2.6,-0.2) J4(-1.8,-0.2) J5(-1.4,-0.2) J6(-1,-0.2) J7(-0.6,-0.2) J8(-0.2,-0.2) J9(0.2,-0.2) J10(0.6,-0.2) J11(1,-0.2) J12(1.4,-0.2) J14(2.2,-0.2) K1(-3,-0.6) K2(-2.6,-0.6) K4(-1.8,-0.6) K6(-1,-0.6) K7(-0.6,-0.6) K8(-0.2,-0.6) K9(0.2,-0.6) K10(0.6,-0.6) K11(1,-0.6) K12(1.4,-0.6) K13(1.8,-0.6) K14(2.2,-0.6) K15(2.6,-0.6) K16(3,-0.6) L3(-2.2,-1) L4(-1.8,-1) L6(-1,-1) L7(-0.6,-1) L8(-0.2,-1) L9(0.2,-1) L10(0.6,-1) L11(1,-1) L12(1.4,-1) L13(1.8,-1) L14(2.2,-1) M1(-3,-1.4) M2(-2.6,-1.4) M4(-1.8,-1.4) M6(-1,-1.4) M7(-0.6,-1.4) M8(-0.2,-1.4) M9(0.2,-1.4) M10(0.6,-1.4) M12(1.4,-1.4) M14(2.2,-1.4) M15(2.6,-1.4) M16(3,-1.4) N1(-3,-1.8) N2(-2.6,-1.8) N3(-2.2,-1.8) N4(-1.8,-1.8) N5(-1.4,-1.8) N6(-1,-1.8) N8(-0.2,-1.8) N11(1,-1.8) N13(1.8,-1.8) N14(2.2,-1.8) N15(2.6,-1.8) N16(3,-1.8) P2(-2.6,-2.2) P3(-2.2,-2.2) P4(-1.8,-2.2) P5(-1.4,-2.2) P8(-0.2,-2.2) P9(0.2,-2.2) P11(1,-2.2) P13(1.8,-2.2) P14(2.2,-2.2) P15(2.6,-2.2) R1(-3,-2.6) R2(-2.6,-2.6) R3(-2.2,-2.6) R4(-1.8,-2.6) R5(-1.4,-2.6) R6(-1,-2.6) R7(-0.6,-2.6) R8(-0.2,-2.6) R9(0.2,-2.6) R10(0.6,-2.6) R11(1,-2.6) R12(1.4,-2.6) R13(1.8,-2.6) R14(2.2,-2.6) R15(2.6,-2.6) R16(3,-2.6) T1(-3,-3) T2(-2.6,-3) T3(-2.2,-3) T5(-1.4,-3) T6(-1,-3) T8(-0.2,-3) T11(1,-3) T13(1.8,-3) T14(2.2,-3) T15(2.6,-3) T16(3,-3)
  Top pour cut-out: 3.4,3.4 -3.4,3.4 -3.4,-3.4 3.4,-3.4 3.4,3.4
  silkscreen extent -3.65,-3.4 3.4,3.65
MT6605$2F$MQFN32$2F$SMD$2F$P0.4$2F$4X4$2F$S [mm]
  rrect0% 0.22x0.22 smd: 1(-1.4,-1.903) 8(1.4,-1.903) 9(1.903,-1.4) 16(1.903,1.4) 17(1.4,1.903) 24(-1.4,1.903) 25(-1.903,1.4) 32(-1.903,-1.4)
  rect 0.22x0.795 smd: 2(-1,-1.903) 3(-0.6,-1.903) 4(-0.2,-1.903) 5(0.2,-1.903) 6(0.6,-1.903) 7(1,-1.903) 18(1,1.903) 19(0.6,1.903) 20(0.2,1.903) 21(-0.2,1.903) 22(-0.6,1.903) 23(-1,1.903)
  rect 0.795x0.22 smd: 10(1.903,-1) 11(1.903,-0.6) 12(1.903,-0.2) 13(1.903,0.2) 14(1.903,0.6) 15(1.903,1) 26(-1.903,1) 27(-1.903,0.6) 28(-1.903,0.2) 29(-1.903,-0.2) 30(-1.903,-0.6) 31(-1.903,-1)
  rect 2.65x2.65 smd: 33(0,0)
  Top region: -1.378,-1.505 -1.29,-1.505 -1.29,-2.3 -1.51,-2.3 -1.51,-1.637 -1.378,-1.505
  Top region: 1.51,-1.637 1.51,-2.3 1.29,-2.3 1.29,-1.505 1.378,-1.505 1.51,-1.637
  Top region: 1.637,-1.51 2.3,-1.51 2.3,-1.29 1.505,-1.29 1.505,-1.378 1.637,-1.51
  Top region: 1.637,1.51 2.3,1.51 2.3,1.29 1.505,1.29 1.505,1.378 1.637,1.51
  Top region: 1.51,1.637 1.51,2.3 1.29,2.3 1.29,1.505 1.378,1.505 1.51,1.637
  Top region: -1.378,1.505 -1.29,1.505 -1.29,2.3 -1.51,2.3 -1.51,1.637 -1.378,1.505
  Top region: -1.505,1.378 -1.505,1.29 -2.3,1.29 -2.3,1.51 -1.637,1.51 -1.505,1.378
  Top region: -1.505,-1.378 -1.505,-1.29 -2.3,-1.29 -2.3,-1.51 -1.637,-1.51 -1.505,-1.378
  silkscreen extent -2.3,-2.3 2.05,2.05
MT6625$2F$SQFN40$2F$SMD$2F$P0.4$2F$5X5 [mm]
  rect 0.22x0.72 smd: 1(-1.8,-2.44) 2(-1.4,-2.44) 3(-1,-2.44) 4(-0.6,-2.44) 5(-0.2,-2.44) 6(0.2,-2.44) 7(0.6,-2.44) 8(1,-2.44) 9(1.4,-2.44) 10(1.8,-2.44) 21(1.8,2.44) 22(1.4,2.44) 23(1,2.44) 24(0.6,2.44) 25(0.2,2.44) 26(-0.2,2.44) 27(-0.6,2.44) 28(-1,2.44) 29(-1.4,2.44) 30(-1.8,2.44)
  rect 0.72x0.22 smd: 11(2.44,-1.8) 12(2.44,-1.4) 13(2.44,-1) 14(2.44,-0.6) 15(2.44,-0.2) 16(2.44,0.2) 17(2.44,0.6) 18(2.44,1) 19(2.44,1.4) 20(2.44,1.8) 31(-2.44,1.8) 32(-2.44,1.4) 33(-2.44,1) 34(-2.44,0.6) 35(-2.44,0.2) 36(-2.44,-0.2) 37(-2.44,-0.6) 38(-2.44,-1) 39(-2.44,-1.4) 40(-2.44,-1.8)
  rect 3.8x3.8 smd: 41(0,0)
  silkscreen extent -2.85,-2.85 2.6,2.6
MT6735$2F$VFBGA641$2F$P0.4$2F$B0.25$2F$12.6X12.6 [mm]
  round 0.25 smd mask+0.038: A1(-6,6) A2(-5.6,6) A3(-5.2,6) A5(-4.4,6) A6(-4,6) A8(-3.2,6) A9(-2.8,6) A11(-2,6) A12(-1.6,6) A14(-0.8,6) A15(-0.4,6) A17(0.4,6) A18(0.8,6) A20(1.6,6) A21(2,6) A23(2.8,6) A24(3.2,6) A26(4,6) A27(4.4,6) A29(5.2,6) A30(5.6,6) A31(6,6) AA2(-5.6,-2) AA5(-4.4,-2) AA7(-3.6,-2) AA8(-3.2,-2) AA9(-2.8,-2) AA10(-2.4,-2) AA11(-2,-2) AA12(-1.6,-2) AA13(-1.2,-2) AA14(-0.8,-2) AA15(-0.4,-2) AA16(0,-2) AA17(0.4,-2) AA18(0.8,-2) AA19(1.2,-2) AA20(1.6,-2) AA21(2,-2) AA22(2.4,-2) AA23(2.8,-2) AA24(3.2,-2) AA28(4.8,-2) AA29(5.2,-2) AA30(5.6,-2) AB1(-6,-2.4) AB2(-5.6,-2.4) AB4(-4.8,-2.4) AB5(-4.4,-2.4) AB7(-3.6,-2.4) AB8(-3.2,-2.4) AB9(-2.8,-2.4) AB10(-2.4,-2.4) AB11(-2,-2.4) AB12(-1.6,-2.4) AB13(-1.2,-2.4) AB14(-0.8,-2.4) AB15(-0.4,-2.4) AB16(0,-2.4) AB17(0.4,-2.4) AB18(0.8,-2.4) AB19(1.2,-2.4) AB20(1.6,-2.4) AB21(2,-2.4) AB22(2.4,-2.4) AB23(2.8,-2.4) AB24(3.2,-2.4) AB27(4.4,-2.4) AB28(4.8,-2.4) AB29(5.2,-2.4) AB30(5.6,-2.4) AB31(6,-2.4) AC1(-6,-2.8) AC2(-5.6,-2.8) AC3(-5.2,-2.8) AC4(-4.8,-2.8) AC7(-3.6,-2.8) AC8(-3.2,-2.8) AC9(-2.8,-2.8) AC10(-2.4,-2.8) AC11(-2,-2.8) AC12(-1.6,-2.8) AC13(-1.2,-2.8) AC14(-0.8,-2.8) AC15(-0.4,-2.8) AC16(0,-2.8) AC17(0.4,-2.8) AC18(0.8,-2.8) AC19(1.2,-2.8) AC20(1.6,-2.8) AC21(2,-2.8) AC22(2.4,-2.8) AC23(2.8,-2.8) AC24(3.2,-2.8) AC27(4.4,-2.8) AC30(5.6,-2.8) AC31(6,-2.8) AD2(-5.6,-3.2) AD3(-5.2,-3.2) AD4(-4.8,-3.2) AD5(-4.4,-3.2) AD27(4.4,-3.2) AD28(4.8,-3.2) AD29(5.2,-3.2) AD30(5.6,-3.2) AE1(-6,-3.6) AE2(-5.6,-3.6) AE5(-4.4,-3.6) AE10(-2.4,-3.6) AE11(-2,-3.6) AE13(-1.2,-3.6) AE14(-0.8,-3.6) AE27(4.4,-3.6) AE28(4.8,-3.6) AE29(5.2,-3.6) AE30(5.6,-3.6) AE31(6,-3.6) AF1(-6,-4) AF2(-5.6,-4) AF5(-4.4,-4) AF20(1.6,-4) AF21(2,-4) AF22(2.4,-4) AF27(4.4,-4) AF28(4.8,-4) AF30(5.6,-4) AF31(6,-4) AG2(-5.6,-4.4) AG3(-5.2,-4.4) AG4(-4.8,-4.4) AG5(-4.4,-4.4) AG6(-4,-4.4) AG7(-3.6,-4.4) AG8(-3.2,-4.4) AG9(-2.8,-4.4) AG11(-2,-4.4) AG12(-1.6,-4.4) AG13(-1.2,-4.4) AG14(-0.8,-4.4) AG15(-0.4,-4.4) AG16(0,-4.4) AG17(0.4,-4.4) AG18(0.8,-4.4) AG19(1.2,-4.4) AG20(1.6,-4.4) AG21(2,-4.4) AG22(2.4,-4.4) AG23(2.8,-4.4) AG24(3.2,-4.4) AG25(3.6,-4.4) AG26(4,-4.4) AG27(4.4,-4.4) AG30(5.6,-4.4) AH1(-6,-4.8) AH2(-5.6,-4.8) AH3(-5.2,-4.8) AH4(-4.8,-4.8) AH5(-4.4,-4.8) AH6(-4,-4.8) AH7(-3.6,-4.8) AH8(-3.2,-4.8) AH9(-2.8,-4.8) AH10(-2.4,-4.8) AH11(-2,-4.8) AH13(-1.2,-4.8) AH14(-0.8,-4.8) AH15(-0.4,-4.8) AH18(0.8,-4.8) AH19(1.2,-4.8) AH21(2,-4.8) AH22(2.4,-4.8) AH23(2.8,-4.8) AH25(3.6,-4.8) AH26(4,-4.8) AH27(4.4,-4.8) AH28(4.8,-4.8) AH29(5.2,-4.8) AH30(5.6,-4.8) AH31(6,-4.8) AJ1(-6,-5.2) AJ2(-5.6,-5.2) AJ3(-5.2,-5.2) AJ4(-4.8,-5.2) AJ5(-4.4,-5.2) AJ6(-4,-5.2) AJ7(-3.6,-5.2) AJ8(-3.2,-5.2) AJ9(-2.8,-5.2) AJ10(-2.4,-5.2) AJ13(-1.2,-5.2) AJ14(-0.8,-5.2) AJ15(-0.4,-5.2) AJ18(0.8,-5.2) AJ19(1.2,-5.2) AJ22(2.4,-5.2) AJ23(2.8,-5.2) AJ26(4,-5.2) AJ27(4.4,-5.2) AJ28(4.8,-5.2) AJ29(5.2,-5.2) AJ30(5.6,-5.2) AJ31(6,-5.2) AK1(-6,-5.6) AK2(-5.6,-5.6) AK3(-5.2,-5.6) AK4(-4.8,-5.6) AK5(-4.4,-5.6) AK6(-4,-5.6) AK7(-3.6,-5.6) AK8(-3.2,-5.6) AK9(-2.8,-5.6) AK10(-2.4,-5.6) AK11(-2,-5.6) AK12(-1.6,-5.6) AK13(-1.2,-5.6) AK14(-0.8,-5.6) AK15(-0.4,-5.6) AK16(0,-5.6) AK17(0.4,-5.6) AK18(0.8,-5.6) AK19(1.2,-5.6) AK20(1.6,-5.6) AK21(2,-5.6) AK22(2.4,-5.6) AK23(2.8,-5.6) AK24(3.2,-5.6) AK25(3.6,-5.6) AK26(4,-5.6) AK27(4.4,-5.6) AK28(4.8,-5.6) AK29(5.2,-5.6) AK30(5.6,-5.6) AL1(-6,-6) AL2(-5.6,-6) AL3(-5.2,-6) AL4(-4.8,-6) AL5(-4.4,-6) AL6(-4,-6) AL8(-3.2,-6) AL9(-2.8,-6) AL10(-2.4,-6) AL12(-1.6,-6) AL14(-0.8,-6) AL15(-0.4,-6) AL17(0.4,-6) AL18(0.8,-6) AL20(1.6,-6) AL21(2,-6) AL23(2.8,-6) AL24(3.2,-6) AL26(4,-6) AL27(4.4,-6) AL29(5.2,-6) AL30(5.6,-6) AL31(6,-6) B1(-6,5.6) B2(-5.6,5.6) B3(-5.2,5.6) B4(-4.8,5.6) B5(-4.4,5.6) B6(-4,5.6) B7(-3.6,5.6) B8(-3.2,5.6) B9(-2.8,5.6) B10(-2.4,5.6) B11(-2,5.6) B12(-1.6,5.6) B13(-1.2,5.6) B14(-0.8,5.6) B15(-0.4,5.6) B16(0,5.6) B17(0.4,5.6) B18(0.8,5.6) B19(1.2,5.6) B20(1.6,5.6) B21(2,5.6) B22(2.4,5.6) B23(2.8,5.6) B24(3.2,5.6) B25(3.6,5.6) B26(4,5.6) B27(4.4,5.6) B28(4.8,5.6) B29(5.2,5.6) B30(5.6,5.6) B31(6,5.6) C2(-5.6,5.2) C3(-5.2,5.2) C6(-4,5.2) C7(-3.6,5.2) C10(-2.4,5.2) C11(-2,5.2) C14(-0.8,5.2) C15(-0.4,5.2) C18(0.8,5.2) C19(1.2,5.2) C22(2.4,5.2) C23(2.8,5.2) C26(4,5.2) C27(4.4,5.2) C28(4.8,5.2) C29(5.2,5.2) C30(5.6,5.2) C31(6,5.2) D1(-6,4.8) D2(-5.6,4.8) D3(-5.2,4.8) D4(-4.8,4.8) D5(-4.4,4.8) D6(-4,4.8) D7(-3.6,4.8) D8(-3.2,4.8) D9(-2.8,4.8) D10(-2.4,4.8) D11(-2,4.8) D12(-1.6,4.8) D14(-0.8,4.8) D15(-0.4,4.8) D17(0.4,4.8) D18(0.8,4.8) D20(1.6,4.8) D21(2,4.8) D23(2.8,4.8) D25(3.6,4.8) D26(4,4.8) D27(4.4,4.8) D28(4.8,4.8) D29(5.2,4.8) D30(5.6,4.8) E1(-6,4.4) E2(-5.6,4.4) E3(-5.2,4.4) E9(-2.8,4.4) E12(-1.6,4.4) E15(-0.4,4.4) E17(0.4,4.4) E20(1.6,4.4) E23(2.8,4.4) E24(3.2,4.4) E25(3.6,4.4) E27(4.4,4.4) E28(4.8,4.4) E30(5.6,4.4) E31(6,4.4) F2(-5.6,4) F3(-5.2,4) F9(-2.8,4) F12(-1.6,4) F15(-0.4,4) F16(0,4) F17(0.4,4) F20(1.6,4) F27(4.4,4) F28(4.8,4) F29(5.2,4) F30(5.6,4) F31(6,4) G1(-6,3.6) G2(-5.6,3.6) G4(-4.8,3.6) G9(-2.8,3.6) G10(-2.4,3.6) G12(-1.6,3.6) G13(-1.2,3.6) G14(-0.8,3.6) G15(-0.4,3.6) G16(0,3.6) G17(0.4,3.6) G18(0.8,3.6) G28(4.8,3.6) G29(5.2,3.6) G30(5.6,3.6) H1(-6,3.2) H2(-5.6,3.2) H3(-5.2,3.2) H4(-4.8,3.2) H9(-2.8,3.2) H10(-2.4,3.2) H12(-1.6,3.2) H13(-1.2,3.2) H14(-0.8,3.2) H15(-0.4,3.2) H16(0,3.2) H17(0.4,3.2) H18(0.8,3.2) H28(4.8,3.2) H29(5.2,3.2) H30(5.6,3.2) H31(6,3.2) J2(-5.6,2.8) J4(-4.8,2.8) J28(4.8,2.8) J29(5.2,2.8) J30(5.6,2.8) J31(6,2.8) K1(-6,2.4) K2(-5.6,2.4) K4(-4.8,2.4) K7(-3.6,2.4) K8(-3.2,2.4) K9(-2.8,2.4) K27(4.4,2.4) K28(4.8,2.4) K30(5.6,2.4) L2(-5.6,2) L3(-5.2,2) L4(-4.8,2) L7(-3.6,2) L8(-3.2,2) L9(-2.8,2) L10(-2.4,2) L11(-2,2) L12(-1.6,2) L13(-1.2,2) L14(-0.8,2) L15(-0.4,2) L16(0,2) L17(0.4,2) L18(0.8,2) L19(1.2,2) L20(1.6,2) L21(2,2) L22(2.4,2) L23(2.8,2) L27(4.4,2) L28(4.8,2) L29(5.2,2) L30(5.6,2) L31(6,2) M1(-6,1.6) M2(-5.6,1.6) M3(-5.2,1.6) M7(-3.6,1.6) M8(-3.2,1.6) M9(-2.8,1.6) M10(-2.4,1.6) M11(-2,1.6) M12(-1.6,1.6) M13(-1.2,1.6) M15(-0.4,1.6) M16(0,1.6) M17(0.4,1.6) M18(0.8,1.6) M19(1.2,1.6) M20(1.6,1.6) M21(2,1.6) M22(2.4,1.6) M23(2.8,1.6) M27(4.4,1.6) M28(4.8,1.6) M30(5.6,1.6) M31(6,1.6) N1(-6,1.2) N2(-5.6,1.2) N3(-5.2,1.2) N7(-3.6,1.2) N8(-3.2,1.2) N9(-2.8,1.2) N10(-2.4,1.2) N11(-2,1.2) N12(-1.6,1.2) N13(-1.2,1.2) N14(-0.8,1.2) N15(-0.4,1.2) N16(0,1.2) N17(0.4,1.2) N18(0.8,1.2) N19(1.2,1.2) N20(1.6,1.2) N21(2,1.2) N22(2.4,1.2) N23(2.8,1.2) N27(4.4,1.2) N28(4.8,1.2) N29(5.2,1.2) N30(5.6,1.2) P2(-5.6,0.8) P3(-5.2,0.8) P7(-3.6,0.8) P8(-3.2,0.8) P9(-2.8,0.8) P10(-2.4,0.8) P11(-2,0.8) P12(-1.6,0.8) P13(-1.2,0.8) P14(-0.8,0.8) P15(-0.4,0.8) P16(0,0.8) P17(0.4,0.8) P18(0.8,0.8) P19(1.2,0.8) P20(1.6,0.8) P21(2,0.8) P28(4.8,0.8) P29(5.2,0.8) P30(5.6,0.8) P31(6,0.8) R1(-6,0.4) R2(-5.6,0.4) R3(-5.2,0.4) R7(-3.6,0.4) R8(-3.2,0.4) R9(-2.8,0.4) R10(-2.4,0.4) R11(-2,0.4) R12(-1.6,0.4) R13(-1.2,0.4) R14(-0.8,0.4) R15(-0.4,0.4) R16(0,0.4) R17(0.4,0.4) R18(0.8,0.4) R19(1.2,0.4) R20(1.6,0.4) R21(2,0.4) R28(4.8,0.4) R29(5.2,0.4) R30(5.6,0.4) T1(-6,0) T2(-5.6,0) T3(-5.2,0) T4(-4.8,0) T7(-3.6,0) T8(-3.2,0) T9(-2.8,0) T10(-2.4,0) T11(-2,0) T12(-1.6,0) T13(-1.2,0) T14(-0.8,0) T15(-0.4,0) T16(0,0) T17(0.4,0) T18(0.8,0) T19(1.2,0) T20(1.6,0) T21(2,0) T22(2.4,0) T23(2.8,0) T28(4.8,0) T29(5.2,0) T30(5.6,0) T31(6,0) U2(-5.6,-0.4) U4(-4.8,-0.4) U7(-3.6,-0.4) U8(-3.2,-0.4) U9(-2.8,-0.4) U10(-2.4,-0.4) U11(-2,-0.4) U12(-1.6,-0.4) U13(-1.2,-0.4) U14(-0.8,-0.4) U15(-0.4,-0.4) U16(0,-0.4) U17(0.4,-0.4) U18(0.8,-0.4) U19(1.2,-0.4) U20(1.6,-0.4) U21(2,-0.4) U22(2.4,-0.4) U23(2.8,-0.4) U28(4.8,-0.4) U29(5.2,-0.4) U30(5.6,-0.4) U31(6,-0.4) V1(-6,-0.8) V2(-5.6,-0.8) V4(-4.8,-0.8) V7(-3.6,-0.8) V8(-3.2,-0.8) V9(-2.8,-0.8) V10(-2.4,-0.8) V11(-2,-0.8) V12(-1.6,-0.8) V13(-1.2,-0.8) V14(-0.8,-0.8) V15(-0.4,-0.8) V16(0,-0.8) V17(0.4,-0.8) V18(0.8,-0.8) V19(1.2,-0.8) V20(1.6,-0.8) V21(2,-0.8) V22(2.4,-0.8) V23(2.8,-0.8) V28(4.8,-0.8) V29(5.2,-0.8) V30(5.6,-0.8) W1(-6,-1.2) W2(-5.6,-1.2) W3(-5.2,-1.2) W4(-4.8,-1.2) W7(-3.6,-1.2) W8(-3.2,-1.2) W9(-2.8,-1.2) W10(-2.4,-1.2) W11(-2,-1.2) W12(-1.6,-1.2) W13(-1.2,-1.2) W14(-0.8,-1.2) W15(-0.4,-1.2) W16(0,-1.2) W17(0.4,-1.2) W18(0.8,-1.2) W19(1.2,-1.2) W20(1.6,-1.2) W21(2,-1.2) W22(2.4,-1.2) W23(2.8,-1.2) W24(3.2,-1.2) W28(4.8,-1.2) W29(5.2,-1.2) W30(5.6,-1.2) W31(6,-1.2) Y1(-6,-1.6) Y2(-5.6,-1.6) Y3(-5.2,-1.6) Y4(-4.8,-1.6) Y7(-3.6,-1.6) Y8(-3.2,-1.6) Y9(-2.8,-1.6) Y10(-2.4,-1.6) Y11(-2,-1.6) Y12(-1.6,-1.6) Y13(-1.2,-1.6) Y14(-0.8,-1.6) Y15(-0.4,-1.6) Y16(0,-1.6) Y17(0.4,-1.6) Y18(0.8,-1.6) Y19(1.2,-1.6) Y20(1.6,-1.6) Y21(2,-1.6) Y22(2.4,-1.6) Y23(2.8,-1.6) Y24(3.2,-1.6) Y27(4.4,-1.6) Y28(4.8,-1.6) Y30(5.6,-1.6) Y31(6,-1.6)
  Top pour cut-out: 6.4,6.4 -6.4,6.4 -6.4,-6.4 6.4,-6.4 6.4,6.4
  silkscreen extent -6.65,-6.4 6.4,6.65
NC$2F$MMD$2F$L1$2F$4MIL [mil]
  rect 4x4 smd: 1(-2,0) 2(2,0)
NC$2F$R [mil]
  rect 10x20 smd: 1(-15,0) 2(15,0)
  Top lines w10: -15,0 3,0 ; 0,0 15,0
PAD$2F$1P$2F$R2.2 [mm]
  round 2.2 smd: 1(0,0)
QFN16$2F$SMD$2F$P0.5$2F$ITG-1010 [mm]
  rect 0.3x0.75 smd: 1(-1,-1.475) 2(-0.5,-1.475) 3(0,-1.475) 4(0.5,-1.475) 5(1,-1.475) 9(1,1.475) 10(0.5,1.475) 11(0,1.475) 12(-0.5,1.475) 13(-1,1.475)
  rect 0.75x0.3 smd: 6(1.475,-0.5) 7(1.475,0) 8(1.475,0.5) 14(-1.475,0.5) 15(-1.475,0) 16(-1.475,-0.5)
  rect 1.85x1.85 smd: 17(0,0)
  silkscreen extent -1.85,-1.85 1.6,1.6
R0201 [mil]
  rect 12x12 smd: 1(-10,0) 2(10,0)
  silkscreen extent -20,-10 20,10
R0201_1-2 [mil]
  rect 12x12 smd: 1(-20,0) 2(0,0) 3(20,0)
  silkscreen extent -30,-10 10,10
R0402 [mil]
  rect 20x20 smd: 1(-18,0) 2(18,0)
  silkscreen extent -33,-15 33,15
R0603 [mil]
  rect 28x32 smd: 1(-25.59,0) 2(25.59,0)
  silkscreen extent -48,-25 48,25
R0805 [mil]
  rect 34x56 smd: 1(-34.45,0) 2(34.45,0)
  silkscreen extent -62,-38 63,38
R1206 [mm]
  rect 1x1.8 smd: 1(-1.4,0) 2(1.4,0)
  silkscreen extent -2.2,-1.2 2.2,1.2
RB160M-30-EVB [mil]
  rect 48x63 smd: 1(-81,0) 2(81,0)
  silkscreen extent -50,-35 122,35
RECEIVE$2F$SMD$2F$NXP [mm]
  rect 1.8x2.6 smd: 1(-3.7,1.1) 2(3.7,-1.1)
  silkscreen extent -4.1,-6.85 4.1,6.85
RF1141A [mm]
  rect 0.2x0.2 smd mask+0.06: 1(-0.635,0.535) 2(-0.635,0) 3(-0.635,-0.535) 4(0,-0.535) 5(0.635,-0.535) 6(0.635,0) 7(0.635,0.535) 8(0,0.535) 9(0,0)
  silkscreen extent -1.15,-0.78 0.88,1.05
RF1628 [mm]
  rect 0.2x0.2 smd mask+0.05: 1(-0.4,-0.4) 2(0,-0.4) 3(0.4,-0.4) 4(0.4,0) 5(0.4,0.4) 6(0,0.4) 7(-0.4,0.4) 8(-0.4,0) 9(0,0)
  silkscreen extent -0.85,-0.85 0.6,0.6
RF7255 [mm]
  rect 0.35x0.35 smd paste-0.018 mask+0.07: 1(-1.225,1.2) 2(-1.225,0.6) 3(-1.225,0) 4(-1.225,-0.6) 5(-1.225,-1.2) 6(1.225,-1.2) 7(1.225,-0.6) 8(1.225,0) 9(1.225,0.6) 10(1.225,1.2)
  rect 1.5x1.5 smd mask+0.72: 11(0,0)
  Top region: -0.75,1.4 0.75,1.4 0.75,-1.4 -0.75,-1.4 -0.75,1.4
  silkscreen extent -1.82,-1.6 1.6,1.83
SAW$2F$8P$2F$SMD$2F$D2.0X1.6$2F$SAYFH833MCA0F00 [mm]
  rect 0.405x0.365 smd: 1(-0.797,-0.617) 3(0.797,-0.617) 5(0.797,0.617) 7(-0.797,0.617)
  rect 0.33x0.365 smd: 2(0,-0.617) 6(0,0.617)
  rect 0.405x0.29 smd: 4(0.797,0) 8(-0.797,0)
  rect 0.29x0.29 smd: 9(0,0)
  Top region: -0.305,-0.145 0.305,-0.145 0.305,0.145 -0.305,0.145 -0.305,-0.145
  silkscreen extent -1.35,-1.15 1.1,0.9
SAW$2F$SMD$2F$1.05X1.35 [mil]
  rect 10.5x13.5 smd: 1(0,0) 2(19.69,-11.32) 3(39.37,-11.32) 4(39.37,11.32) 5(19.69,11.32)
  silkscreen extent -12,-27 55,27
SAWFILTER$2F$SMD$2F$F6QB2G595P2BS [mm]
  rect 0.35x0.35 smd: 1(-0.475,0)
  rect 0.24x0.375 smd: 2(0,-0.288) 5(0,0.288)
  rect 0.25x0.375 smd: 3(0.425,-0.288) 4(0.425,0.288)
  silkscreen extent -0.9,-0.55 0.65,0.55
SAWFILTER$2F$SMD$2F$SAWFD1G90BH0F0A [mm]
  rect 0.255x0.25 smd: 1(-0.623,-0.425) 4(0.623,-0.425) 6(0.623,0.425) 9(-0.623,0.425)
  rect 0.18x0.25 smd: 2(-0.195,-0.425) 3(0.195,-0.425) 7(0.195,0.425) 8(-0.195,0.425)
  rect 0.465x0.18 smd: 5(0.52,0)
  rect 0.565x0.18 smd: 10(-0.47,0)
  silkscreen extent -0.97,-0.76 0.83,0.63
SB$2F$0201 [mil]
  rect 12x12 smd: 1(-9,0) 2(9,0)
  Top region: -15,6 0,6 0,-6 -15,-6 -15,6
  Top region: 15,6 0,6 0,-6 15,-6 15,6
  silkscreen extent -21,-10 21,10
SB$2F$0402 [mil]
  rect 22x20 smd: 1(-17,0) 2(17,0)
  Top region: -28,10 0,10 0,-10 -28,-10 -28,10
  Top region: 28,-10 0,-10 0,10 28,10 28,-10
  silkscreen extent -33,-15 33,15
SB$2F$0603 [mil]
  rect 28x32 smd: 1(-25.59,0) 2(25.59,0)
  Top region: -39.6,16 0,16 0,-16 -39.6,-16 -39.6,16
  Top region: 0,16 39.6,16 39.6,-16 0,-16 0,16
  silkscreen extent -48,-25 48,25
SHIELD_CAN_CLIP$2F$3P$2F$SMD$2F$PTV3121N [mm]
  rect 1.48x0.8 smd: 1(-1.51,0) 3(1.51,0)
  rect 1.25x0.8 smd: 2(0,0)
  silkscreen extent -2.35,-0.5 2.35,0.5
SHIELD_CAN_CLIP$2F$PTV0703B [mm]
  rect 0.6x0.9 smd: 1(-3.05,0) 5(3.05,0)
  rect 1.5x0.9 smd: 2(-1.65,0) 4(1.65,0)
  rect 1.2x0.9 smd: 3(0,0)
  silkscreen extent -3.5,-0.55 3.5,0.55
SIM$2F$10P$2F$SMD$2F$SCGD1B0307 [mm]
  rect 0.45x1 smd: 1(3.255,0) 2(0.055,0) 3(-1.145,0) 4(-2.345,0) 5(2.655,0) 6(-0.545,0) 7(-1.745,0) 8(-2.945,0) 9(0.655,0) 10(-3.545,0)
  rect 0.75x1.1 smd: 11(-4.8,0.12) 12(5.51,0.12)
  rect 0.37x1.25 smd: 13(-7.165,-2.875)
  rect 0.37x1.6 smd: 14(7.165,-2.24)
  rect 0.37x1.5 smd: 15(7.165,-9.1) 16(-7.165,-9.1)
  rect 1x1.1 smd: 17(-6.85,-14.92)
  rect 0.85x1.1 smd: 18(6.925,-14.92)
  silkscreen extent -7.6,-15.7 7.6,0.95
SKY13418 [mm]
  rect 0.2x0.395 smd: 1(-0.675,-0.953) 2(-0.225,-0.953) 3(0.225,-0.953) 4(0.675,-0.953) 8(0.675,0.953) 9(0.225,0.953) 10(-0.225,0.953) 11(-0.675,0.953)
  rect 0.395x0.2 smd: 5(0.953,-0.4) 6(0.953,0) 7(0.953,0.4) 12(-0.953,0.4) 13(-0.953,0) 14(-0.953,-0.4)
  rect 1x1 smd: 15(0,0)
  silkscreen extent -1.3,-1.3 1.05,1.05
SKY13489 [mm]
  round 0.25 smd: 1(0.2,0.4) 2(-0.2,0.4) 3(-0.2,0) 4(-0.2,-0.4) 5(0.2,-0.4) 6(0.2,0)
  silkscreen extent -0.4,-0.6 0.55,0.75
SKY77643 [mm]
  rect 0.29x0.5 smd mask+0.05: 1(-3.15,-1.75) 8(0,-1.75) 15(3.15,-1.75) 22(3.15,1.75) 29(0,1.75) 36(-3.15,1.75)
  rect 0.22x0.5 smd mask+0.05: 2(-2.675,-1.75) 3(-2.235,-1.75) 4(-1.795,-1.75) 5(-1.355,-1.75) 6(-0.915,-1.75) 7(-0.475,-1.75) 9(0.475,-1.75) 10(0.915,-1.75) 11(1.355,-1.75) 12(1.795,-1.75) 13(2.235,-1.75) 14(2.675,-1.75) 23(2.675,1.75) 24(2.235,1.75) 25(1.795,1.75) 26(1.355,1.75) 27(0.915,1.75) 28(0.475,1.75) 30(-0.475,1.75) 31(-0.915,1.75) 32(-1.355,1.75) 33(-1.795,1.75) 34(-2.235,1.75) 35(-2.675,1.75)
  rect 0.5x0.22 smd mask+0.05: 16(3.15,-1.1) 17(3.15,-0.66) 18(3.15,-0.22) 19(3.15,0.22) 20(3.15,0.66) 21(3.15,1.1) 37(-3.15,1.1) 38(-3.15,0.66) 39(-3.15,0.22) 40(-3.15,-0.22) 41(-3.15,-0.66) 42(-3.15,-1.1) 43(0,1.1) 44(0,0.66) 45(0,0.22) 46(0,-0.22) 47(0,-0.66) 48(0,-1.1)
  rect 0.85x1 smd: 49(-1.025,0.637) 50(1.025,0.637)
  Top region: 1.45,1.138 0.6,1.138 0.6,0.138 1.45,0.138 1.45,1.138
  Top region: 2.55,1.138 1.7,1.138 1.7,0.138 2.55,0.138 2.55,1.138
  Top region: 1.45,-0.138 0.6,-0.138 0.6,-1.138 1.45,-1.138 1.45,-0.138
  Top region: 2.55,-0.138 1.7,-0.138 1.7,-1.138 2.55,-1.138 2.55,-0.138
  Top region: -0.6,1.138 -1.45,1.138 -1.45,0.138 -0.6,0.138 -0.6,1.138
  Top region: -1.7,1.138 -2.55,1.138 -2.55,0.138 -1.7,0.138 -1.7,1.138
  Top region: -1.7,-0.138 -2.55,-0.138 -2.55,-1.138 -1.7,-1.138 -1.7,-0.138
  Top region: -0.6,-0.138 -1.45,-0.138 -1.45,-1.138 -0.6,-1.138 -0.6,-0.138
  silkscreen extent -3.7,-2.3 3.45,2.05
SKY77910 [mm]
  rect 0.23x0.65 smd mask+0.05: 1(-2.4,-2.475) 2(-1.92,-2.475) 3(-1.44,-2.475) 4(-0.96,-2.475) 5(-0.48,-2.475) 6(0,-2.475) 7(0.48,-2.475) 8(0.96,-2.475) 9(1.44,-2.475) 10(1.92,-2.475) 11(2.4,-2.475) 20(2.4,2.475) 21(1.92,2.475) 22(1.44,2.475) 23(0.96,2.475) 24(0.48,2.475) 25(0,2.475) 26(-0.48,2.475) 27(-0.96,2.475) 28(-1.44,2.475) 29(-1.92,2.475) 30(-2.4,2.475)
  rect 0.65x0.23 smd mask+0.05: 12(2.575,-1.68) 13(2.575,-1.2) 14(2.575,-0.72) 15(2.575,-0.24) 16(2.575,0.24) 17(2.575,0.72) 18(2.575,1.2) 19(2.575,1.68) 31(-2.575,1.68) 32(-2.575,1.2) 33(-2.575,0.72) 34(-2.575,0.24) 35(-2.575,-0.24) 36(-2.575,-0.72) 37(-2.575,-1.2) 38(-2.575,-1.68)
  rect 1.075x1 smd: 39(0,0)
  Top region: -0.537,0.5 0.537,0.5 0.537,-0.5 -0.537,-0.5 -0.537,0.5
  Top region: 0.813,0.5 1.887,0.5 1.887,-0.5 0.813,-0.5 0.813,0.5
  Top region: -1.887,0.5 -0.813,0.5 -0.813,-0.5 -1.887,-0.5 -1.887,0.5
  Top region: -1.887,1.79 -0.813,1.79 -0.813,0.79 -1.887,0.79 -1.887,1.79
  Top region: -0.537,1.79 0.537,1.79 0.537,0.79 -0.537,0.79 -0.537,1.79
  Top region: 0.813,1.79 1.887,1.79 1.887,0.79 0.813,0.79 0.813,1.79
  Top region: -1.887,-0.79 -0.813,-0.79 -0.813,-1.79 -1.887,-1.79 -1.887,-0.79
  Top region: -0.537,-0.79 0.537,-0.79 0.537,-1.79 -0.537,-1.79 -0.537,-0.79
  Top region: 0.813,-0.79 1.887,-0.79 1.887,-1.79 0.813,-1.79 0.813,-0.79
  silkscreen extent -3.05,-2.95 2.8,2.7
SOD882$2F$SMD$2F$PESD5V0S1BL [mm]
  rect 0.575x0.51 smd: 1(-0.467,0) 2(0.467,0)
  silkscreen extent -0.56,-0.36 0.56,0.36
SON6$2F$SMD$2F$P0.65$2F$TPS61161 [mm]
  rect 0.3x0.7 smd paste-0.025 mask+0.07: 1(-0.65,-1.05) 2(0,-1.05) 3(0.65,-1.05) 4(0.65,1.05) 5(0,1.05) 6(-0.65,1.05)
  rect 1.6x1 smd: 7(0,0)
  silkscreen extent -1.35,-1.35 1.1,1.1
SOT-6 [mm]
  rect 0.6x1 smd: 1(-0.95,-1.25) 2(0,-1.25) 3(0.95,-1.25) 4(0.95,1.25) 5(0,1.25) 6(-0.95,1.25)
  silkscreen extent -1.86,-1.5 1.55,0.77
SPEAKER$2F$SMD$2F$2403-260-00071 [mm]
  rect 1.4x2 smd: 1(-8.1,4.6) 2(8.1,4.6)
  silkscreen extent -9.55,-6.55 9.55,6.55
TCXO3225 [mm]
  rect 1.4x1.15 smd: 1(-1.1,-0.8) 2(1.1,-0.8) 3(1.1,0.8) 4(-1.1,0.8)
  silkscreen extent -2.05,-1.6 1.6,1.25
TCXO$2F$SMD$2F$2.5X2.0$2F$IT2205BE [mm]
  rect 0.78x0.79 smd: 1(-0.965,-0.72) 2(0.965,-0.72) 3(0.965,0.72) 4(-0.965,0.72)
  silkscreen extent -1.65,-1.4 1.4,1.15
TCXO$2F$SMD$2F$2.5X2.0$2F$KT2520F [mm]
  rect 0.5x0.825 smd: 1(-1.15,-0.737) 3(1.15,-0.737) 4(1.15,0.737) 6(-1.15,0.737)
  rect 0.7x0.43 smd: 2(0,-0.935) 5(0,0.935)
  silkscreen extent -1.6,-1.35 1.38,1.12
TP30MIL [mil]
  round 30 smd: 1(0,0)
  silkscreen extent -20,-20 20,20
TP$2F$SMD$2F$12MIL [mil]
  round 12 smd: 1(0,0)
  silkscreen extent -10,-10 10,10
TSLP6$2F$SMD$2F$P0.4$2F$BGA725L6$2F$S [mm]
  rect 0.2x0.5 smd: 1(-0.4,-0.35) 2(0,-0.35) 3(0.4,-0.35) 4(0.4,0.35) 5(0,0.35) 6(-0.4,0.35)
  silkscreen extent -0.85,-0.67 0.62,0.42
UQFN20$2F$SMD$2F$P0.4$2F$CXM3599UR [mm]
  rect 0.2x0.3 smd: 1(-0.8,-1.2) 2(-0.4,-1.2) 3(0,-1.2) 4(0.4,-1.2) 5(0.8,-1.2) 11(0.8,1.2) 12(0.4,1.2) 13(0,1.2) 14(-0.4,1.2) 15(-0.8,1.2)
  rect 0.3x0.2 smd: 6(1.2,-0.8) 7(1.2,-0.4) 8(1.2,0) 9(1.2,0.4) 10(1.2,0.8) 16(-1.2,0.8) 17(-1.2,0.4) 18(-1.2,0) 19(-1.2,-0.4) 20(-1.2,-0.8)
  rect 1.5x1.5 smd paste-0.15 mask+0.05: 21(0,0)
  Top region: -0.7,-1.35 -0.96,-1.35 -0.96,-1.11 -0.9,-1.05 -0.7,-1.05 -0.7,-1.35
  Top region: 0.7,-1.35 0.96,-1.35 0.96,-1.11 0.9,-1.05 0.7,-1.05 0.7,-1.35
  Top region: 1.35,-0.7 1.35,-0.96 1.11,-0.96 1.05,-0.9 1.05,-0.7 1.35,-0.7
  Top region: 1.35,0.7 1.35,0.96 1.11,0.96 1.05,0.9 1.05,0.7 1.35,0.7
  Top region: 0.7,1.35 0.96,1.35 0.96,1.11 0.9,1.05 0.7,1.05 0.7,1.35
  Top region: -0.7,1.35 -0.96,1.35 -0.96,1.11 -0.9,1.05 -0.7,1.05 -0.7,1.35
  Top region: -1.35,0.7 -1.35,0.96 -1.11,0.96 -1.05,0.9 -1.05,0.7 -1.35,0.7
  Top region: -1.35,-0.7 -1.35,-0.96 -1.11,-0.96 -1.05,-0.9 -1.05,-0.7 -1.35,-0.7
  silkscreen extent -1.55,-1.55 1.3,1.3
VMT3$2F$SMD$2F$RUM003N02 [mm]
  rect 0.4x0.45 smd: 1(-0.4,-0.575) 2(0.4,-0.575)
  rect 0.5x0.45 smd: 3(0,0.575)
  silkscreen extent -0.65,-0.45 0.65,0.45
WDFN8$2F$SMD$2F$P0.5$2F$NCP6324 [mm]
  rect 0.3x0.5 smd: 1(-0.75,-0.9) 2(-0.25,-0.9) 3(0.25,-0.9) 4(0.75,-0.9) 5(0.75,0.9) 6(0.25,0.9) 7(-0.25,0.9) 8(-0.75,0.9)
  rect 1x1 smd: 9(0,0)
  Top region: 0.85,0.5 -0.85,0.5 -0.85,-0.5 0.85,-0.5 0.85,0.5
  silkscreen extent -1.3,-1.3 1.05,1.05
WLCSP6$2F$P0.4$2F$B0.2$2F$FAN53611 [mm]
  round 0.2 smd mask+0.05: A1(-0.2,0.4) A2(0.2,0.4) B1(-0.2,0) B2(0.2,0) C1(-0.2,-0.4) C2(0.2,-0.4)
  silkscreen extent -0.74,-0.64 0.5,0.89
WLCSP8$2F$SMD$2F$P0.4$2F$B0.25$2F$AK09911 [mm]
  round 0.25 smd: A1(-0.4,0.4) A2(0,0.4) A3(0.4,0.4) B1(-0.4,0) B3(0.4,0) C1(-0.4,-0.4) C2(0,-0.4) C3(0.4,-0.4)
  silkscreen extent -0.96,-0.71 0.71,0.96

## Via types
v1: diameter 12, hole 4, Top to Inner Layer 2, 3329 vias
v2: diameter 12, hole 4, Inner Layer 5 to Bottom, 3071 vias
v3: diameter 18, hole 10, Inner Layer 2 to Inner Layer 5, 1928 vias
v4: diameter 10, hole 4, Top to Inner Layer 2, 525 vias
v5: diameter 20, hole 12, Top to Bottom, 472 vias

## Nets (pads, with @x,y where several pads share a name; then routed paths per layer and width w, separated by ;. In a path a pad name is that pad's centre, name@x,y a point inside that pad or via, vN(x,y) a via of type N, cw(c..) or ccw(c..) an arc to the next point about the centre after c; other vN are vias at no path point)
32K_EN: R3108.1 U3101.J2 | length 111.6
  Top w4: v1(1885.38,4090.31) 1884.65,4091.04 1886.65,4091.04 R3108.1@1886.65,4091.09
  Inner Layer 2 w4: v1(1885.38,4090.31) 1884.65,4091.04 1880.65,4087.04 1880.65,4032.3 1878.37,4030.02 1878.37,4017.59 1895.16,4000.81 v4(1895.16,3993.08)
32K_IN: C2034.1 R2030.1 U2001.T6 X2001.2 | length 248.5
  Top w4: X2001.2@692.31,3329.3 699.71,3336.69 739.31,3297.09 C2034.1@743.31,3297.09 743.95,3296.45 743.95,3295.49 745.12,3295.49 745.12,3296.66 756.95,3284.83 756.95,3230.96 760.83,3227.09 761.31,3227.09 R2030.1@769.31,3219.09 769.31,3216.09 799.31,3186.09 824.31,3186.09 829.31,3181.09 836.84,3181.09 U2001.T6@836.84,3180.2
32K_OUT: C2033.1 U2001.R6 X2001.1 | length 196.3
  Top w4: X2001.1@692.31,3230.88 742.99,3230.87 C2033.1@743.95,3231.83 751.69,3224.09 752.38,3224.09 756.31,3220.15 756.31,3211.6 790.83,3177.09 821.55,3177.09 829.55,3169.09 841.48,3169.09 U2001.R6@852.59,3180.2
ACCDET: R6030.1 U2001.M14 | length 899.7
  Inner Layer 2 w4: v4(899.83,3054.22) 900.52,3054.9 917.61,3037.81 v3(918.29,3038.5)
  Inner Layer 5 w4: v2(310.31,2740.09) 300.31,2750.09 300.31,2846.14 352.56,2898.39 v2(364.73,2898.39) ; v2(835.12,3052.6) 904.18,3052.6 v3(918.29,3038.5)
  Bottom w4: v2(310.31,2740.09) 333.81,2740.09 341.81,2748.09 R6030.1@341.81,2756.09 ; R6030.1@341.67,2751.69 341.67,2756.09 R6030.1@341.81,2756.09 ; R6030.1@343.31,2756.09 R6030.1@341.81,2756.09 ; v2(364.73,2898.39) 371.03,2892.09 564.31,2892.09 724.83,3052.6 v2(835.12,3052.6)
ADD1: CON3303.2 R3305.2 | length 55.3
  Top w4: CON3303.2@2345.3,3086.47 2345.3,3077.09 CON3303.2@2346.3,3087.48 ; CON3303.2@2345.3,3086.47 CON3303.2@2346.3,3087.48 ; CON3303.2@2345.3,3086.47 CON3303.2@2346.3,3087.48
  Top w5: CON3303.2@2346.3,3087.48 R3305.2@2346.3,3120.09
ADD5: C3318.2 CON3301.2 L3346.1 | length 313.8
  Top w5: v1(2343.3,3163.09) L3346.1@2365.3,3163.09
  Inner Layer 2 w4: v3(2327.31,3188.09) 2343.3,3172.1 v1(2343.3,3163.09)
  Inner Layer 5 w4: v3(2327.31,3188.09) 2327.31,3187.59 2344.31,3187.59 v2(2344.31,3187.09)
  Bottom w5: v2(2344.31,3187.09) 2396.31,3187.09 2439.31,3230.09 CON3301.2@2439.31,3359.42
ADD6: C3318.1 L3317.1 R3305.1 | length 46
  Top w5: C3318.1@2323.3,3163.09 2324.31,3163.09 2324.31,3151.1 L3317.1@2324.3,3140.09 R3305.1@2346.3,3140.09
ANT_N: C5102.2 U5101.26 | length 350.5
  Top w4: C5102.2@357.31,2133.72 C5102.2@357.31,2140.09
  Top w6: C5102.2@357.31,2140.09 320.41,2103.19 320.41,2024.94 342.34,2003.02 387.65,2003.02 393.74,1996.92 393.74,1892.46 397.75,1888.46 U5101.26@416.4,1888.46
